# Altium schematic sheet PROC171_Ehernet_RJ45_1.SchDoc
size 431 x 279 mm; Date: Not shown in title block; ApprovedBy: Not shown in title block; CheckedBy: Not shown in title block; Author: Not shown in title block; CompanyName: Not shown in title block; Engineer: Not shown in title block; Organization: Not shown in title block; Address1: Not shown in title block; Address2: Not shown in title block; Address3: Not shown in title block; Address4: Not shown in title block; DocumentNumber: 19; Revision: Use project parameter SCH_Rev; SheetNumber: 19; SheetTotal: 27; PageSetup: Record=PageOptions¦CenterHorizontal=True¦CenterVertical=True¦PrintScale=1.00¦XCorrection=1.00¦YCorrection=1.00¦PrintKind=0¦BorderSize=5000000¦LeftOffset=0¦BottomOffset=0¦Orientation=2¦PaperLength=1000¦PaperWidth=1000¦Scale=100¦PaperSource=15¦PrintQuality=600¦MediaType=1¦DitherType=10¦PaperKind=Letter¦PrintScaleMode=1
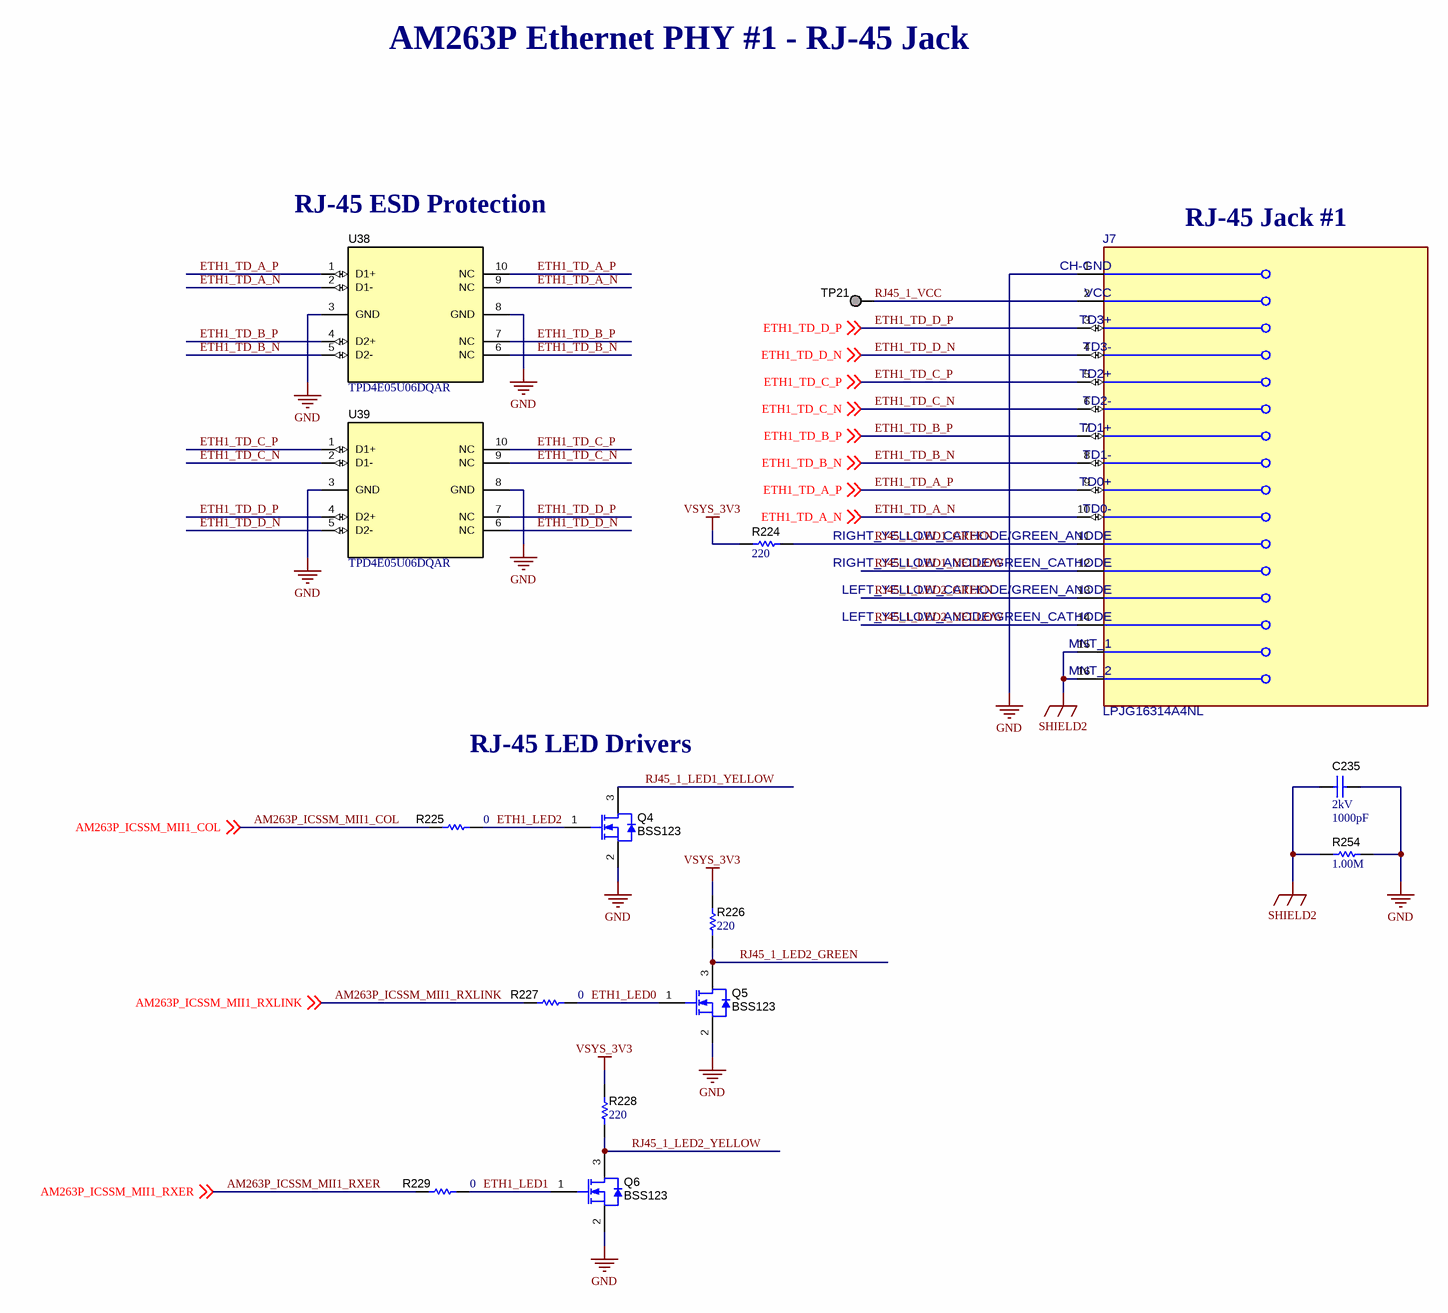
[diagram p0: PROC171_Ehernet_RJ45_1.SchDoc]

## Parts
C235  VDC_V: 2kV  ValueDisplayed: 1000pF  [1808]  (hidden comment: GR442QR73D102KW01L)
J7  LPJG16314A4NL  [FP-LPJG16314A4NL_CONN_RJ45-MFG]
Q4  BSS123  [SOT-23]
Q5  BSS123  [SOT-23]
Q6  BSS123  [SOT-23]
R224  ValueDisplayed: 220  [0402]  (hidden comment: CRCW0402220RJNED)
R225  ValueDisplayed: 0  [0402L]  (hidden comment: ERJ-2GE0R00X)
R226  ValueDisplayed: 220  [0402]  (hidden comment: CRCW0402220RJNED)
R227  ValueDisplayed: 0  [0402L]  (hidden comment: ERJ-2GE0R00X)
R228  ValueDisplayed: 220  [0402]  (hidden comment: CRCW0402220RJNED)
R229  ValueDisplayed: 0  [0402L]  (hidden comment: ERJ-2GE0R00X)
R254  ValueDisplayed: 1.00M  [0805_HV]  (hidden comment: ERJ-6ENF1004V)
TP21  TESTPOINT  [TP_25MIL-SMT]  (value not drawn)  (no BOM)
U38  TPD4E05U06DQAR  [DQA0010A]
U39  TPD4E05U06DQAR  [DQA0010A]

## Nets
GND: C235.1 J7.1(CH-GND) Q4.2(S) Q5.2(S) Q6.2(S) R254.2 U38.3(GND) U38.8(GND) U39.3(GND) U39.8(GND)
SHIELD2: C235.2 J7.15(MNT_1) J7.16(MNT_2) R254.1
VSYS_3V3: R224.1 R226.2 R228.2
AM263P_ICSSM_MII1_COL: R225.2 ; off-sheet AM263P_ICSSM_MII1_COL
AM263P_ICSSM_MII1_RXER: R229.2 ; off-sheet AM263P_ICSSM_MII1_RXER
AM263P_ICSSM_MII1_RXLINK: R227.2 ; off-sheet AM263P_ICSSM_MII1_RXLINK
ETH1_LED0: Q5.1(G) R227.1
ETH1_LED1: Q6.1(G) R229.1
ETH1_LED2: Q4.1(G) R225.1
ETH1_TD_A_N: J7.10(TD0-) U38.2(D1-) U38.9(NC) ; off-sheet ETH1_TD_A_N
ETH1_TD_A_P: J7.9(TD0+) U38.1(D1+) U38.10(NC) ; off-sheet ETH1_TD_A_P
ETH1_TD_B_N: J7.8(TD1-) U38.5(D2-) U38.6(NC) ; off-sheet ETH1_TD_B_N
ETH1_TD_B_P: J7.7(TD1+) U38.4(D2+) U38.7(NC) ; off-sheet ETH1_TD_B_P
ETH1_TD_C_N: J7.6(TD2-) U39.2(D1-) U39.9(NC) ; off-sheet ETH1_TD_C_N
ETH1_TD_C_P: J7.5(TD2+) U39.1(D1+) U39.10(NC) ; off-sheet ETH1_TD_C_P
ETH1_TD_D_N: J7.4(TD3-) U39.5(D2-) U39.6(NC) ; off-sheet ETH1_TD_D_N
ETH1_TD_D_P: J7.3(TD3+) U39.4(D2+) U39.7(NC) ; off-sheet ETH1_TD_D_P
RJ45_1_LED1_GREEN: J7.11(RIGHT_YELLOW_CATHODE/GREEN_ANODE) R224.2
RJ45_1_LED1_YELLOW: J7.12(RIGHT_YELLOW_ANODE/GREEN_CATHODE) Q4.3(D)
RJ45_1_LED2_GREEN: J7.13(LEFT_YELLOW_CATHODE/GREEN_ANODE) Q5.3(D) R226.1
RJ45_1_LED2_YELLOW: J7.14(LEFT_YELLOW_ANODE/GREEN_CATHODE) Q6.3(D) R228.1
RJ45_1_VCC: J7.2(VCC) TP21.1

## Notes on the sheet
- AM263P Ethernet PHY #1 - RJ-45 Jack
- RJ-45 ESD Protection
- RJ-45 Jack #1
- RJ-45 LED Drivers

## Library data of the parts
C235 = CMP-0009436-2: CAP, CERM, 1000 pF, 2000 V, +/- 10%, X7R, 1808; Manufacturer: MuRata; TaMin_C: -55°C; Polarized: N; SizeAreaWB_mm2: 16.5; Value1: Unknown; U/M: EA; Value: 1000pF; TaMax_C: 125°C; SizeZ_mm: 2.03; SizeX_mm: 4.5; SizeY_mm: 2; Value2: 2000V; SizeArea_mm2: 9; Cap_F: 1nF; AEC Category: Q200
J7 = CMP-0093483-1: RJ45 Connector with 1000 Base-TX Inetgrated Magnetic; Manufacturer: Link-PP; SizeZ_mm: 13.7mm; AEC Qualified: No; DUT-Pitch_mm: 1.27mm; Conn Gender: Female; Is Female: yes; ContactFinish: Gold; Conn Orientation: Horizontal
Q4-Q6 = CMP-0000947-2: MOSFET, N-CH, 100 V, 0.17 A, SOT-23; Alternate Manufacturer: None; Manufacturer: Fairchild Semiconductor; SizeZ_mm: 1.1; ChType: N; Value2: 1.8 nC; Value1: 1; VdsMax_V: 100V; SizeX_mm: 2.5; SizeY_mm: 3; Vgs_V: 20V; Value: 100V; Rdson45_ohm: 10; SizeArea_mm2: 7.5; AEC Category: Q101; IdsMax_A: 1.7dA; SizeAreaWB_mm2: 14; U/M: EA; QgTyp_nC: 1.8
R224 R226 R228 = CMP-0026878-3: RES, 220, 5%, 0.063 W, AEC-Q200 Grade 0, 0402; Manufacturer: Vishay-Dale; Power_W: 63mW; TempCo: 200 ppm/C; Value_Code: 220R; Value: 220; EIA_Code: E24; SizeX_mm: 1; SizeY_mm: 0.5; SizeZ_mm: 0.6; Value2: 0.063W; AEC Qualified: Y; VDC_V: 50V; AEC Category: Q200; AEC Grade: 0
R225 R227 R229 = CMP-0026992-3: RES, 0, 5%, 0.1 W, AEC-Q200 Grade 0, 0402; Manufacturer: Panasonic; Power_W: 100mW; TempCo: 600 ppm/C; Value_Code: 0000; Value: 0; EIA_Code: E24; SizeX_mm: 1; SizeY_mm: 0.5; SizeZ_mm: 0.6; Value2: 0.1W; AEC Qualified: Y; VDC_V: 50V; AEC Category: Q200; SizeAreaWB_mm2: 3
R254 = CMP-0021522-3: RES, 1.00 M, 1%, 0.125 W, AEC-Q200 Grade 0, 0805; Manufacturer: Panasonic; Power_W: 125mW; TempCo: 100 ppm/C; Value_Code: 1M00; Value: 1.00Meg; EIA_Code: E96; Res_ohm: 1M; SizeX_mm: 2; SizeY_mm: 1.25; SizeZ_mm: 1.45; Value2: 0.125W; SizeArea_mm2: 2.5; AEC Qualified: Y; AEC Category: Q200; AEC Grade: 0; SizeAreaWB_mm2: 6.75
TP21 = CMP-0078143-3: TEST POINT.  No entry in BOM.
U38 U39 = CMP-0073613-3: 4-Channel Ultra-Low-Capacitance IEC ESD Protection Diode, DQA0010A (USON-10); Alternate Manufacturer: Texas Instruments; Green_Lifecycle: Active; SizeAreaWB_mm2: 7.0; Green_REACh: Passed; SizeZ_mm: 0.55; SizeX_mm: 1.0; SizeY_mm: 2.5; CompType: IC; AEC Category: Q200; AEC Qualified: N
